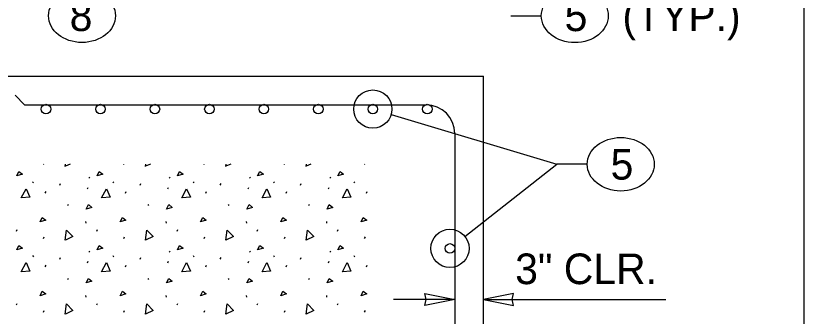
# Model space of a CAD drawing. Extents: x 99862 to 103151, y 100000 to 102076.
# Drawn here: x 102737.5 to 103150, y 100751.6 to 100908.5 of the extents above; entities that cross this region are included whole.
import ezdxf

# ---------------------------------------------------------------- set-up
doc = ezdxf.new("R2010")
doc.units = 0
for name, color, linetype in [('Level 10', 7, 'Continuous'), ('Level 15', 7, 'Continuous'), ('Level 2', 7, 'Continuous'), ('Level 20', 7, 'Continuous'), ('Level 23', 7, 'Continuous'), ('Level 60', 7, 'Continuous')]:
    doc.layers.add(name, color=color, linetype=linetype)

msp = doc.modelspace()

# ---------------------------------------------------------------- linework, layer by layer
at = {"layer": 'Level 10'}
for p, q in [((102737.17, 100866.99), (102742.17, 100861.99)), ((102742.17, 100861.99), (102952.17, 100861.99)), ((102967.17, 100846.99), (102967.17, 100726.99))]:
    msp.add_line(p, q, dxfattribs=at)
for centre in [(102753.32, 100859.77), (102753.32, 100859.77), (102781.82, 100859.77), (102781.82, 100859.77), (102810.32, 100859.77), (102810.32, 100859.77), (102838.82, 100859.77), (102838.82, 100859.77), (102867.32, 100859.77), (102867.32, 100859.77), (102895.82, 100859.77), (102895.82, 100859.77), (102924.32, 100859.77), (102924.32, 100859.77), (102952.82, 100859.77), (102952.82, 100859.77), (102964.67, 100786.99), (102964.67, 100786.99)]:
    msp.add_circle(centre, 2.5, dxfattribs=at)
msp.add_arc((102952.17, 100846.99), 15, 0, 90, dxfattribs=at)
at = {"layer": 'Level 15'}
for p, q in [((102996.46, 100908.51), (103012.46, 100908.51)), ((102996.46, 100908.51), (103012.46, 100908.51)), ((102933.9, 100856.9), (103020.51, 100830.94)), ((102933.9, 100856.9), (103020.51, 100830.94)), ((102972.53, 100793.18), (103020.51, 100830.94)), ((102972.53, 100793.18), (103020.51, 100830.94)), ((103036.51, 100830.94), (103020.51, 100830.94)), ((103036.51, 100830.94), (103020.51, 100830.94)), ((102967.17, 100760.33), (102935.17, 100760.33)), ((102967.17, 100760.33), (102935.17, 100760.33)), ((102982.17, 100760.33), (103077.63, 100760.33)), ((102982.17, 100760.33), (103077.63, 100760.33))]:
    msp.add_line(p, q, dxfattribs=at)
for points in [[(102967.17, 100760.33), (102951.45, 100757.24), (102952.17, 100760.33), (102951.45, 100763.41)], [(102967.17, 100760.33), (102951.45, 100757.24), (102952.17, 100760.33), (102951.45, 100763.41)], [(102982.17, 100760.33), (102997.9, 100757.24), (102997.17, 100760.33), (102997.9, 100763.41)], [(102982.17, 100760.33), (102997.9, 100757.24), (102997.17, 100760.33), (102997.9, 100763.41)]]:
    msp.add_lwpolyline(points, close=True, dxfattribs=at)
for centre in [(102924.32, 100859.77), (102924.32, 100859.77), (102964.67, 100786.99), (102964.67, 100786.99)]:
    msp.add_circle(centre, 10, dxfattribs=at)
at = {"layer": 'Level 2'}
for p in [(102382.17, 100876.99), (102382.17, 100876.99), (102982.17, 100696.99), (102982.17, 100696.99)]:
    msp.add_line(p, (102982.17, 100876.99), dxfattribs=at)
at = {"layer": 'Level 20'}
for centre in [(102772.17, 100908.54), (103029.96, 100908.51), (103054.01, 100830.94)]:
    msp.add_ellipse(centre, major_axis=(-17.5, 0), ratio=0.8, dxfattribs=at)
at = {"layer": 'Level 23'}
for p, q in [((102752.04, 100830.82), (102752.14, 100831.03)), ((102752.04, 100830.82), (102752.14, 100831.03)), ((102794.04, 100830.82), (102794.14, 100831.03)), ((102794.04, 100830.82), (102794.14, 100831.03)), ((102836.04, 100830.82), (102836.14, 100831.03)), ((102836.04, 100830.82), (102836.14, 100831.03)), ((102878.04, 100830.82), (102878.14, 100831.03)), ((102878.04, 100830.82), (102878.14, 100831.03)), ((102920.04, 100830.82), (102920.14, 100831.03)), ((102920.04, 100830.82), (102920.14, 100831.03)), ((102746.34, 100821.82), (102746.71, 100821.27)), ((102746.34, 100821.82), (102746.71, 100821.27)), ((102775.78, 100824.2), (102776.15, 100823.64)), ((102775.78, 100824.2), (102776.15, 100823.64)), ((102788.34, 100821.82), (102788.71, 100821.27)), ((102788.34, 100821.82), (102788.71, 100821.27)), ((102817.78, 100824.2), (102818.15, 100823.64)), ((102817.78, 100824.2), (102818.15, 100823.64)), ((102830.34, 100821.82), (102830.71, 100821.27)), ((102830.34, 100821.82), (102830.71, 100821.27)), ((102859.78, 100824.2), (102860.15, 100823.64)), ((102859.78, 100824.2), (102860.15, 100823.64)), ((102872.34, 100821.82), (102872.71, 100821.27)), ((102872.34, 100821.82), (102872.71, 100821.27)), ((102901.78, 100824.2), (102902.15, 100823.64)), ((102901.78, 100824.2), (102902.15, 100823.64)), ((102914.34, 100821.82), (102914.71, 100821.27)), ((102914.34, 100821.82), (102914.71, 100821.27)), ((102760.53, 100820), (102760.9, 100820.84)), ((102760.53, 100820), (102760.9, 100820.84)), ((102775.07, 100818.05), (102775.45, 100818.89)), ((102775.07, 100818.05), (102775.45, 100818.89)), ((102802.53, 100820), (102802.9, 100820.84)), ((102802.53, 100820), (102802.9, 100820.84)), ((102817.07, 100818.05), (102817.45, 100818.89)), ((102817.07, 100818.05), (102817.45, 100818.89)), ((102844.53, 100820), (102844.9, 100820.84)), ((102844.53, 100820), (102844.9, 100820.84)), ((102859.07, 100818.05), (102859.45, 100818.89)), ((102859.07, 100818.05), (102859.45, 100818.89)), ((102886.53, 100820), (102886.9, 100820.84)), ((102886.53, 100820), (102886.9, 100820.84)), ((102901.07, 100818.05), (102901.45, 100818.89)), ((102901.07, 100818.05), (102901.45, 100818.89)), ((102752.97, 100815.91), (102753.35, 100816.75)), ((102752.97, 100815.91), (102753.35, 100816.75)), ((102794.97, 100815.91), (102795.35, 100816.75)), ((102794.97, 100815.91), (102795.35, 100816.75)), ((102836.97, 100815.91), (102837.35, 100816.75)), ((102836.97, 100815.91), (102837.35, 100816.75)), ((102878.97, 100815.91), (102879.35, 100816.75)), ((102878.97, 100815.91), (102879.35, 100816.75)), ((102920.97, 100815.91), (102921.35, 100816.75)), ((102920.97, 100815.91), (102921.35, 100816.75)), ((102764.63, 100809.94), (102765, 100809.38)), ((102764.63, 100809.94), (102765, 100809.38)), ((102806.63, 100809.94), (102807, 100809.38)), ((102806.63, 100809.94), (102807, 100809.38)), ((102848.63, 100809.94), (102849, 100809.38)), ((102848.63, 100809.94), (102849, 100809.38)), ((102890.63, 100809.94), (102891, 100809.38)), ((102890.63, 100809.94), (102891, 100809.38)), ((102774.06, 100801), (102774.15, 100800.16)), ((102774.06, 100801), (102774.15, 100800.16)), ((102816.06, 100801), (102816.15, 100800.16)), ((102816.06, 100801), (102816.15, 100800.16)), ((102858.06, 100801), (102858.15, 100800.16)), ((102858.06, 100801), (102858.15, 100800.16)), ((102900.06, 100801), (102900.15, 100800.16)), ((102900.06, 100801), (102900.15, 100800.16)), ((102737.87, 100796.05), (102738.24, 100796.89)), ((102737.87, 100796.05), (102738.24, 100796.89)), ((102752.04, 100792.23), (102752.42, 100793.07)), ((102752.04, 100792.23), (102752.42, 100793.07)), ((102779.87, 100796.05), (102780.24, 100796.89)), ((102779.87, 100796.05), (102780.24, 100796.89)), ((102794.04, 100792.23), (102794.42, 100793.07)), ((102794.04, 100792.23), (102794.42, 100793.07)), ((102821.87, 100796.05), (102822.24, 100796.89)), ((102821.87, 100796.05), (102822.24, 100796.89)), ((102836.04, 100792.23), (102836.42, 100793.07)), ((102836.04, 100792.23), (102836.42, 100793.07)), ((102863.87, 100796.05), (102864.24, 100796.89)), ((102863.87, 100796.05), (102864.24, 100796.89)), ((102878.04, 100792.23), (102878.42, 100793.07)), ((102878.04, 100792.23), (102878.42, 100793.07)), ((102905.87, 100796.05), (102906.24, 100796.89)), ((102905.87, 100796.05), (102906.24, 100796.89)), ((102920.04, 100792.23), (102920.42, 100793.07)), ((102920.04, 100792.23), (102920.42, 100793.07)), ((102775.78, 100785.61), (102776.15, 100785.05)), ((102775.78, 100785.61), (102776.15, 100785.05)), ((102817.78, 100785.61), (102818.15, 100785.05)), ((102817.78, 100785.61), (102818.15, 100785.05)), ((102859.78, 100785.61), (102860.15, 100785.05)), ((102859.78, 100785.61), (102860.15, 100785.05)), ((102901.78, 100785.61), (102902.15, 100785.05)), ((102901.78, 100785.61), (102902.15, 100785.05)), ((102746.34, 100783.24), (102746.71, 100782.68)), ((102746.34, 100783.24), (102746.71, 100782.68)), ((102760.53, 100781.41), (102760.9, 100782.25)), ((102760.53, 100781.41), (102760.9, 100782.25)), ((102788.34, 100783.24), (102788.71, 100782.68)), ((102788.34, 100783.24), (102788.71, 100782.68)), ((102802.53, 100781.41), (102802.9, 100782.25)), ((102802.53, 100781.41), (102802.9, 100782.25)), ((102830.34, 100783.24), (102830.71, 100782.68)), ((102830.34, 100783.24), (102830.71, 100782.68)), ((102844.53, 100781.41), (102844.9, 100782.25)), ((102844.53, 100781.41), (102844.9, 100782.25)), ((102872.34, 100783.24), (102872.71, 100782.68)), ((102872.34, 100783.24), (102872.71, 100782.68)), ((102886.53, 100781.41), (102886.9, 100782.25)), ((102886.53, 100781.41), (102886.9, 100782.25)), ((102914.34, 100783.24), (102914.71, 100782.68)), ((102914.34, 100783.24), (102914.71, 100782.68)), ((102752.97, 100777.32), (102753.35, 100778.16)), ((102752.97, 100777.32), (102753.35, 100778.16)), ((102775.07, 100779.46), (102775.45, 100780.3)), ((102775.07, 100779.46), (102775.45, 100780.3)), ((102794.97, 100777.32), (102795.35, 100778.16)), ((102794.97, 100777.32), (102795.35, 100778.16)), ((102817.07, 100779.46), (102817.45, 100780.3)), ((102817.07, 100779.46), (102817.45, 100780.3)), ((102836.97, 100777.32), (102837.35, 100778.16)), ((102836.97, 100777.32), (102837.35, 100778.16)), ((102859.07, 100779.46), (102859.45, 100780.3)), ((102859.07, 100779.46), (102859.45, 100780.3)), ((102878.97, 100777.32), (102879.35, 100778.16)), ((102878.97, 100777.32), (102879.35, 100778.16)), ((102901.07, 100779.46), (102901.45, 100780.3)), ((102901.07, 100779.46), (102901.45, 100780.3)), ((102920.97, 100777.32), (102921.35, 100778.16)), ((102920.97, 100777.32), (102921.35, 100778.16)), ((102764.63, 100771.35), (102765, 100770.79)), ((102764.63, 100771.35), (102765, 100770.79)), ((102806.63, 100771.35), (102807, 100770.79)), ((102806.63, 100771.35), (102807, 100770.79)), ((102848.63, 100771.35), (102849, 100770.79)), ((102848.63, 100771.35), (102849, 100770.79)), ((102890.63, 100771.35), (102891, 100770.79)), ((102890.63, 100771.35), (102891, 100770.79)), ((102774.06, 100762.41), (102774.15, 100761.57)), ((102774.06, 100762.41), (102774.15, 100761.57)), ((102816.06, 100762.41), (102816.15, 100761.57)), ((102816.06, 100762.41), (102816.15, 100761.57)), ((102858.06, 100762.41), (102858.15, 100761.57)), ((102858.06, 100762.41), (102858.15, 100761.57)), ((102900.06, 100762.41), (102900.15, 100761.57)), ((102900.06, 100762.41), (102900.15, 100761.57)), ((102737.87, 100757.46), (102738.24, 100758.3)), ((102737.87, 100757.46), (102738.24, 100758.3)), ((102779.87, 100757.46), (102780.24, 100758.3)), ((102779.87, 100757.46), (102780.24, 100758.3)), ((102821.87, 100757.46), (102822.24, 100758.3)), ((102821.87, 100757.46), (102822.24, 100758.3)), ((102863.87, 100757.46), (102864.24, 100758.3)), ((102863.87, 100757.46), (102864.24, 100758.3)), ((102905.87, 100757.46), (102906.24, 100758.3)), ((102905.87, 100757.46), (102906.24, 100758.3)), ((102752.04, 100753.64), (102752.42, 100754.48)), ((102752.04, 100753.64), (102752.42, 100754.48)), ((102794.04, 100753.64), (102794.42, 100754.48)), ((102794.04, 100753.64), (102794.42, 100754.48)), ((102836.04, 100753.64), (102836.42, 100754.48)), ((102836.04, 100753.64), (102836.42, 100754.48)), ((102878.04, 100753.64), (102878.42, 100754.48)), ((102878.04, 100753.64), (102878.42, 100754.48)), ((102920.04, 100753.64), (102920.42, 100754.48)), ((102920.04, 100753.64), (102920.42, 100754.48))]:
    msp.add_line(p, q, dxfattribs=at)
for points in [[(102763.38, 100829.85), (102763.55, 100831.03)], [(102763.38, 100829.85), (102763.55, 100831.03)], [(102765.96, 100831.03), (102763.47, 100829.88)], [(102765.96, 100831.03), (102763.47, 100829.88)], [(102805.38, 100829.85), (102805.55, 100831.03)], [(102805.38, 100829.85), (102805.55, 100831.03)], [(102807.96, 100831.03), (102805.47, 100829.88)], [(102807.96, 100831.03), (102805.47, 100829.88)], [(102847.38, 100829.85), (102847.55, 100831.03)], [(102847.38, 100829.85), (102847.55, 100831.03)], [(102849.96, 100831.03), (102847.47, 100829.88)], [(102849.96, 100831.03), (102847.47, 100829.88)], [(102889.38, 100829.85), (102889.55, 100831.03)], [(102889.38, 100829.85), (102889.55, 100831.03)], [(102891.96, 100831.03), (102889.47, 100829.88)], [(102891.96, 100831.03), (102889.47, 100829.88)], [(102738.06, 100824.85), (102739.17, 100827.18), (102741.04, 100825.78), (102738.06, 100824.85)], [(102738.06, 100824.85), (102739.17, 100827.18), (102741.04, 100825.78), (102738.06, 100824.85)], [(102780.06, 100824.85), (102781.17, 100827.18), (102783.04, 100825.78), (102780.06, 100824.85)], [(102780.06, 100824.85), (102781.17, 100827.18), (102783.04, 100825.78), (102780.06, 100824.85)], [(102822.06, 100824.85), (102823.17, 100827.18), (102825.04, 100825.78), (102822.06, 100824.85)], [(102822.06, 100824.85), (102823.17, 100827.18), (102825.04, 100825.78), (102822.06, 100824.85)], [(102864.06, 100824.85), (102865.17, 100827.18), (102867.04, 100825.78), (102864.06, 100824.85)], [(102864.06, 100824.85), (102865.17, 100827.18), (102867.04, 100825.78), (102864.06, 100824.85)], [(102906.06, 100824.85), (102907.17, 100827.18), (102909.04, 100825.78), (102906.06, 100824.85)], [(102906.06, 100824.85), (102907.17, 100827.18), (102909.04, 100825.78), (102906.06, 100824.85)], [(102740.39, 100813.39), (102742.9, 100818.15), (102744.86, 100813.77), (102740.48, 100813.39)], [(102740.39, 100813.39), (102742.9, 100818.15), (102744.86, 100813.77), (102740.48, 100813.39)], [(102782.39, 100813.39), (102784.9, 100818.15), (102786.86, 100813.77), (102782.48, 100813.39)], [(102782.39, 100813.39), (102784.9, 100818.15), (102786.86, 100813.77), (102782.48, 100813.39)], [(102824.39, 100813.39), (102826.9, 100818.15), (102828.86, 100813.77), (102824.48, 100813.39)], [(102824.39, 100813.39), (102826.9, 100818.15), (102828.86, 100813.77), (102824.48, 100813.39)], [(102866.39, 100813.39), (102868.9, 100818.15), (102870.86, 100813.77), (102866.48, 100813.39)], [(102866.39, 100813.39), (102868.9, 100818.15), (102870.86, 100813.77), (102866.48, 100813.39)], [(102908.39, 100813.39), (102910.9, 100818.15), (102912.86, 100813.77), (102908.48, 100813.39)], [(102908.39, 100813.39), (102910.9, 100818.15), (102912.86, 100813.77), (102908.48, 100813.39)], [(102774.42, 100807.52), (102775.54, 100809.85), (102777.4, 100808.45), (102774.42, 100807.52)], [(102774.42, 100807.52), (102775.54, 100809.85), (102777.4, 100808.45), (102774.42, 100807.52)], [(102816.42, 100807.52), (102817.54, 100809.85), (102819.4, 100808.45), (102816.42, 100807.52)], [(102816.42, 100807.52), (102817.54, 100809.85), (102819.4, 100808.45), (102816.42, 100807.52)], [(102858.42, 100807.52), (102859.54, 100809.85), (102861.4, 100808.45), (102858.42, 100807.52)], [(102858.42, 100807.52), (102859.54, 100809.85), (102861.4, 100808.45), (102858.42, 100807.52)], [(102900.42, 100807.52), (102901.54, 100809.85), (102903.4, 100808.45), (102900.42, 100807.52)], [(102900.42, 100807.52), (102901.54, 100809.85), (102903.4, 100808.45), (102900.42, 100807.52)], [(102750.2, 100800.85), (102751.32, 100803.18), (102753.18, 100801.78), (102750.2, 100800.85)], [(102750.2, 100800.85), (102751.32, 100803.18), (102753.18, 100801.78), (102750.2, 100800.85)], [(102792.2, 100800.85), (102793.32, 100803.18), (102795.18, 100801.78), (102792.2, 100800.85)], [(102792.2, 100800.85), (102793.32, 100803.18), (102795.18, 100801.78), (102792.2, 100800.85)], [(102834.2, 100800.85), (102835.32, 100803.18), (102837.18, 100801.78), (102834.2, 100800.85)], [(102834.2, 100800.85), (102835.32, 100803.18), (102837.18, 100801.78), (102834.2, 100800.85)], [(102876.2, 100800.85), (102877.32, 100803.18), (102879.18, 100801.78), (102876.2, 100800.85)], [(102876.2, 100800.85), (102877.32, 100803.18), (102879.18, 100801.78), (102876.2, 100800.85)], [(102918.2, 100800.85), (102919.32, 100803.18), (102921.18, 100801.78), (102918.2, 100800.85)], [(102918.2, 100800.85), (102919.32, 100803.18), (102921.18, 100801.78), (102918.2, 100800.85)], [(102763.38, 100791.26), (102764.13, 100796.59), (102767.46, 100793.14), (102763.47, 100791.29)], [(102763.38, 100791.26), (102764.13, 100796.59), (102767.46, 100793.14), (102763.47, 100791.29)], [(102805.38, 100791.26), (102806.13, 100796.59), (102809.46, 100793.14), (102805.47, 100791.29)], [(102805.38, 100791.26), (102806.13, 100796.59), (102809.46, 100793.14), (102805.47, 100791.29)], [(102847.38, 100791.26), (102848.13, 100796.59), (102851.46, 100793.14), (102847.47, 100791.29)], [(102847.38, 100791.26), (102848.13, 100796.59), (102851.46, 100793.14), (102847.47, 100791.29)], [(102889.38, 100791.26), (102890.13, 100796.59), (102893.46, 100793.14), (102889.47, 100791.29)], [(102889.38, 100791.26), (102890.13, 100796.59), (102893.46, 100793.14), (102889.47, 100791.29)], [(102738.06, 100786.26), (102739.17, 100788.59), (102741.04, 100787.19), (102738.06, 100786.26)], [(102738.06, 100786.26), (102739.17, 100788.59), (102741.04, 100787.19), (102738.06, 100786.26)], [(102780.06, 100786.26), (102781.17, 100788.59), (102783.04, 100787.19), (102780.06, 100786.26)], [(102780.06, 100786.26), (102781.17, 100788.59), (102783.04, 100787.19), (102780.06, 100786.26)], [(102822.06, 100786.26), (102823.17, 100788.59), (102825.04, 100787.19), (102822.06, 100786.26)], [(102822.06, 100786.26), (102823.17, 100788.59), (102825.04, 100787.19), (102822.06, 100786.26)], [(102864.06, 100786.26), (102865.17, 100788.59), (102867.04, 100787.19), (102864.06, 100786.26)], [(102864.06, 100786.26), (102865.17, 100788.59), (102867.04, 100787.19), (102864.06, 100786.26)], [(102906.06, 100786.26), (102907.17, 100788.59), (102909.04, 100787.19), (102906.06, 100786.26)], [(102906.06, 100786.26), (102907.17, 100788.59), (102909.04, 100787.19), (102906.06, 100786.26)], [(102740.39, 100774.81), (102742.9, 100779.56), (102744.86, 100775.18), (102740.48, 100774.81)], [(102740.39, 100774.81), (102742.9, 100779.56), (102744.86, 100775.18), (102740.48, 100774.81)], [(102782.39, 100774.81), (102784.9, 100779.56), (102786.86, 100775.18), (102782.48, 100774.81)], [(102782.39, 100774.81), (102784.9, 100779.56), (102786.86, 100775.18), (102782.48, 100774.81)], [(102824.39, 100774.81), (102826.9, 100779.56), (102828.86, 100775.18), (102824.48, 100774.81)], [(102824.39, 100774.81), (102826.9, 100779.56), (102828.86, 100775.18), (102824.48, 100774.81)], [(102866.39, 100774.81), (102868.9, 100779.56), (102870.86, 100775.18), (102866.48, 100774.81)], [(102866.39, 100774.81), (102868.9, 100779.56), (102870.86, 100775.18), (102866.48, 100774.81)], [(102908.39, 100774.81), (102910.9, 100779.56), (102912.86, 100775.18), (102908.48, 100774.81)], [(102908.39, 100774.81), (102910.9, 100779.56), (102912.86, 100775.18), (102908.48, 100774.81)], [(102774.42, 100768.93), (102775.54, 100771.26), (102777.4, 100769.86), (102774.42, 100768.93)], [(102774.42, 100768.93), (102775.54, 100771.26), (102777.4, 100769.86), (102774.42, 100768.93)], [(102816.42, 100768.93), (102817.54, 100771.26), (102819.4, 100769.86), (102816.42, 100768.93)], [(102816.42, 100768.93), (102817.54, 100771.26), (102819.4, 100769.86), (102816.42, 100768.93)], [(102858.42, 100768.93), (102859.54, 100771.26), (102861.4, 100769.86), (102858.42, 100768.93)], [(102858.42, 100768.93), (102859.54, 100771.26), (102861.4, 100769.86), (102858.42, 100768.93)], [(102900.42, 100768.93), (102901.54, 100771.26), (102903.4, 100769.86), (102900.42, 100768.93)], [(102900.42, 100768.93), (102901.54, 100771.26), (102903.4, 100769.86), (102900.42, 100768.93)], [(102750.2, 100762.26), (102751.32, 100764.59), (102753.18, 100763.2), (102750.2, 100762.26)], [(102750.2, 100762.26), (102751.32, 100764.59), (102753.18, 100763.2), (102750.2, 100762.26)], [(102792.2, 100762.26), (102793.32, 100764.59), (102795.18, 100763.2), (102792.2, 100762.26)], [(102792.2, 100762.26), (102793.32, 100764.59), (102795.18, 100763.2), (102792.2, 100762.26)], [(102834.2, 100762.26), (102835.32, 100764.59), (102837.18, 100763.2), (102834.2, 100762.26)], [(102834.2, 100762.26), (102835.32, 100764.59), (102837.18, 100763.2), (102834.2, 100762.26)], [(102876.2, 100762.26), (102877.32, 100764.59), (102879.18, 100763.2), (102876.2, 100762.26)], [(102876.2, 100762.26), (102877.32, 100764.59), (102879.18, 100763.2), (102876.2, 100762.26)], [(102918.2, 100762.26), (102919.32, 100764.59), (102921.18, 100763.2), (102918.2, 100762.26)], [(102918.2, 100762.26), (102919.32, 100764.59), (102921.18, 100763.2), (102918.2, 100762.26)], [(102763.38, 100752.67), (102764.13, 100758), (102767.46, 100754.55), (102763.47, 100752.7)], [(102763.38, 100752.67), (102764.13, 100758), (102767.46, 100754.55), (102763.47, 100752.7)], [(102805.38, 100752.67), (102806.13, 100758), (102809.46, 100754.55), (102805.47, 100752.7)], [(102805.38, 100752.67), (102806.13, 100758), (102809.46, 100754.55), (102805.47, 100752.7)], [(102847.38, 100752.67), (102848.13, 100758), (102851.46, 100754.55), (102847.47, 100752.7)], [(102847.38, 100752.67), (102848.13, 100758), (102851.46, 100754.55), (102847.47, 100752.7)], [(102889.38, 100752.67), (102890.13, 100758), (102893.46, 100754.55), (102889.47, 100752.7)], [(102889.38, 100752.67), (102890.13, 100758), (102893.46, 100754.55), (102889.47, 100752.7)]]:
    msp.add_lwpolyline(points, dxfattribs=at)
at = {"layer": 'Level 60'}
msp.add_line((103150, 100000), (103150, 102075), dxfattribs=at)

# ---------------------------------------------------------------- texts
at = {"layer": 'Level 20'}
for s, p in [('8', (102765.71, 100900.54)), ('(TYP.)', (103054.91, 100900.48))]:
    msp.add_text(s, height=16, dxfattribs=at).set_placement(p)
for s, p in [('5', (103024.65, 100900.51)), ('5', (103048.7, 100822.94)), ('3" CLR.', (102998.78, 100768.33))]:
    msp.add_text(s, height=16, rotation=360, dxfattribs=at).set_placement(p)

doc.saveas('drawing.dxf')
